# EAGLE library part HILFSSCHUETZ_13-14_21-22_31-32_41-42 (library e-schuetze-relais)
Hilfsschütz mit 1 Schließer, 3 Öffnern
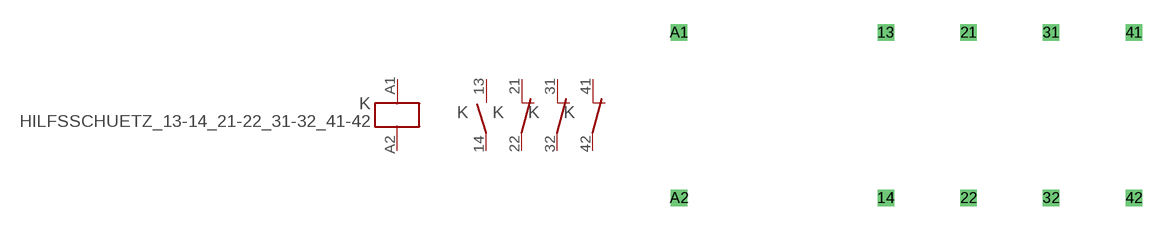
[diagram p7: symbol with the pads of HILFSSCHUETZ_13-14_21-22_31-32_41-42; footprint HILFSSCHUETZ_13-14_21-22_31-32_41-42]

Designator prefix K; gates G$1=SPULE 1=SCHLIESSER 2=OEFFNER 3=OEFFNER 4=OEFFNER

## HILFSSCHUETZ_13-14_21-22_31-32_41-42  [HILFSSCHUETZ_13-14_21-22_31-32_41-42]
13  1:3  pas
14  1:4  pas
21  2:1  pas
22  2:2  pas
31  3:1  pas
32  3:2  pas
41  4:1  pas
42  4:2  pas
A1  G$1:A1  in
A2  G$1:A2  in

## Footprint HILFSSCHUETZ_13-14_21-22_31-32_41-42 (pad centres in mm)
Dummy
drill 0.5 pad 1 square: 13 2.54,5.08; 14 2.54,-5.08; 21 7.62,5.08; 22 7.62,-5.08; 31 12.7,5.08; 32 12.7,-5.08; 41 17.78,5.08; 42 17.78,-5.08; A1 -10.16,5.08; A2 -10.16,-5.08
